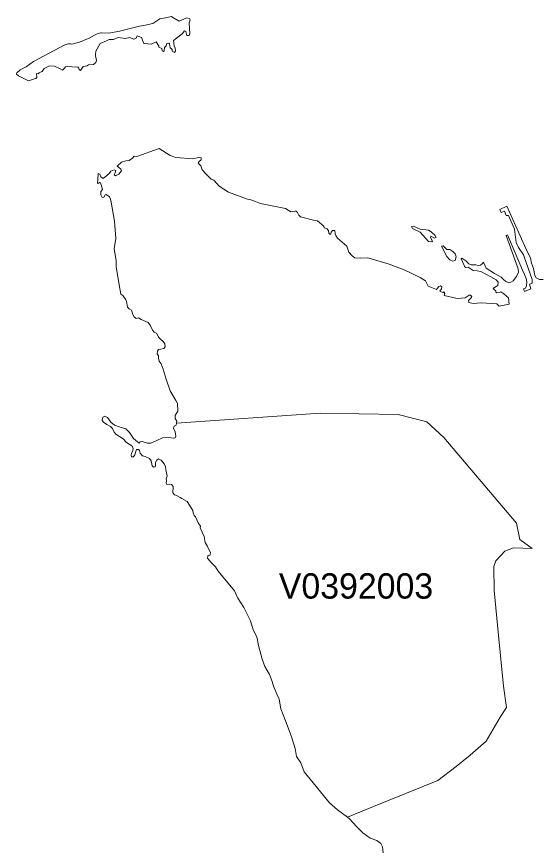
# Model space of a CAD drawing. Extents: x 369010 to 735936, y 6377141 to 6616555.
# Drawn here: x 409820 to 411897, y 6537827 to 6541117 of the extents above; entities that cross this region are included whole.
import ezdxf
from ezdxf.enums import TextEntityAlignment as Align

# ---------------------------------------------------------------- set-up
doc = ezdxf.new("R2010")
doc.units = 0
doc.header["$LTSCALE"] = 40
doc.layers.add('3', color=7, linetype='Continuous', lineweight=13)
doc.layers.add('4', color=7, linetype='Continuous')

msp = doc.modelspace()

# ---------------------------------------------------------------- linework, layer by layer
at = {"layer": '3'}
for points in [[(410420.8, 6541012.78), (410423.94, 6541009.31), (410426.26, 6540994.08), (410431.39, 6540989.12), (410433.87, 6540986.8), (410434.7, 6540981.17), (410442.97, 6540975.71), (410447.11, 6540981.5), (410447.11, 6540981.5), (410446.45, 6540992.26), (410446.45, 6540992.26), (410441.98, 6541001.03), (410439.5, 6541023.21), (410450.75, 6541031.65), (410473.43, 6541048.86), (410483.19, 6541060.28), (410488.32, 6541057.64), (410488.49, 6541057.64), (410491.63, 6541041.91), (410491.63, 6541041.91), (410501.56, 6541043.07), (410504.04, 6541048.53), (410500.9, 6541092.23), (410504.71, 6541104.8), (410502.72, 6541109.94), (410502.72, 6541109.94), (410491.14, 6541111.76), (410480.71, 6541107.29), (410461.84, 6541099.34), (410461.68, 6541099.18), (410436.35, 6541114.07), (410431.55, 6541116.89), (410412.69, 6541113.25), (410407.39, 6541112.09), (410385.71, 6541107.95), (410357.57, 6541089.25), (410327.29, 6541083.62), (410304.45, 6541079.48), (410231.79, 6541060.78), (410226.83, 6541059.46)], [(410226.83, 6541059.46), (410182.64, 6541052.01), (410155.49, 6541052.84), (410151.85, 6541053), (410138.12, 6541049.36), (410137.62, 6541049.2), (410127.19, 6541043.4), (410105.51, 6541031.32), (410067.94, 6541015.76), (410036.99, 6541008.81), (410032.19, 6541009.14), (410023.92, 6541009.81), (410009.68, 6541005.01), (409967.81, 6540982.99), (409885.72, 6540939.63), (409857.26, 6540919.27), (409833.75, 6540907.03), (409820.18, 6540895.28), (409819.52, 6540890.31), (409827.13, 6540882.7), (409827.13, 6540882.7), (409867.02, 6540863.67), (409877.78, 6540866.98), (409894.16, 6540871.94), (409895.49, 6540872.27), (409899.62, 6540876.08), (409897.47, 6540892.79), (409904.92, 6540891.14), (409904.92, 6540891.14), (409907.9, 6540894.28), (409919.65, 6540900.08), (409919.82, 6540900.08), (409928.42, 6540911.5), (409928.42, 6540911.5), (409946.79, 6540920.93), (409949.61, 6540922.42), (409969.47, 6540921.59), (409991.31, 6540910.5), (410000.58, 6540905.7), (410008.19, 6540913.81), (410012.5, 6540918.45), (410018.95, 6540920.27), (410060, 6540917.45), (410064.47, 6540916.79), (410066.29, 6540907.69), (410071.91, 6540903.88), (410072.08, 6540903.88), (410077.38, 6540912.32), (410082.51, 6540920.6), (410082.51, 6540920.6), (410098.56, 6540922.75), (410099.88, 6540923.74), (410103.03, 6540926.23), (410123.22, 6540927.55), (410123.22, 6540927.55), (410132.16, 6540935.49), (410135.14, 6540943.11), (410132.65, 6540956.35), (410131.83, 6540961.15), (410130.67, 6540967.11), (410132.98, 6540981.01), (410149.37, 6541010.8), (410174.36, 6541021.89), (410185.45, 6541026.85), (410189.92, 6541026.85), (410202.17, 6541026.85), (410204.98, 6541028.01), (410220.21, 6541034.47), (410250, 6541031.16), (410266.38, 6541033.97), (410281.94, 6541028.01), (410282.93, 6541027.68), (410291.37, 6541031.49), (410295.84, 6541040.59), (410295.84, 6541040.59), (410302.13, 6541038.77), (410313.22, 6541034.96), (410313.22, 6541034.96), (410319.67, 6541017.75), (410321.49, 6541012.95), (410322.16, 6541011.13), (410325.13, 6541010.8), (410351.28, 6541008.32), (410370.81, 6541016.92), (410380.74, 6541003.52), (410380.91, 6541003.35), (410381.57, 6540996.73), (410381.57, 6540996.73), (410392.99, 6540991.27), (410394.65, 6540982.33), (410394.65, 6540982.17), (410399.78, 6540979.19), (410399.94, 6540979.02), (410403.09, 6540982.17), (410403.75, 6540995.41), (410410.37, 6541002.03), (410412.36, 6541009.97), (410414.67, 6541010.8), (410420.8, 6541012.78), (410420.8, 6541012.78)], [(410599.21, 6540471.09), (410588.45, 6540474.57), (410579.18, 6540484.5), (410569.09, 6540493.93), (410552.37, 6540511.97), (410547.74, 6540528.02), (410542.44, 6540532.66), (410536.32, 6540539.44), (410540.29, 6540544.74), (410548.4, 6540550.7), (410548.4, 6540558.81), (410537.64, 6540560.13), (410516.29, 6540554.84), (410448.1, 6540560.79), (410426.75, 6540568.24), (410383.23, 6540595.55), (410294.35, 6540564.77), (410283.59, 6540565.43), (410277.64, 6540557.48), (410264.23, 6540548.71), (410250.82, 6540547.39), (410234.11, 6540541.43), (410217.39, 6540526.04), (410222.69, 6540522.07), (410231.46, 6540513.96), (410233.45, 6540508), (410223.35, 6540493.93), (410210.11, 6540487.97), (410204.65, 6540491.94), (410208.62, 6540499.89), (410211.43, 6540509.32), (410205.31, 6540511.97), (410191.9, 6540506.01), (410185.95, 6540498.56), (410176.51, 6540488.63), (410161.95, 6540477.88), (410151.85, 6540484.5), (410147.88, 6540494.59), (410141.76, 6540496.58), (410140.43, 6540471.92), (410139.11, 6540460.5), (410141.76, 6540457.85), (410147.22, 6540461.16), (410151.19, 6540459.84), (410155.16, 6540449.08), (410158.47, 6540434.35), (410152.51, 6540425.74), (410151.85, 6540412.34), (410157.15, 6540402.24), (410164.6, 6540403.56), (410169.23, 6540412.34), (410173.86, 6540413.66), (410185.95, 6540404.89), (410190.58, 6540396.28), (410193.23, 6540383.54), (410206.63, 6540309.23), (410212.1, 6540240.38), (410205.31, 6540199.66), (410212.76, 6540152.83), (410212.76, 6540129.32), (410224.67, 6540057.16), (410230.8, 6540021.08), (410238.74, 6540014.96), (410250.82, 6539998.25), (410254.13, 6539992.95), (410258.11, 6539968.79), (410264.89, 6539962.17), (410272.84, 6539957.53), (410278.3, 6539940.15), (410284.26, 6539931.38), (410291.54, 6539924.1), (410301.63, 6539927.41), (410311.73, 6539920.62), (410339.7, 6539908.71), (410347.15, 6539897.95), (410356.42, 6539877.92), (410363.2, 6539870.48), (410373.13, 6539864.52), (410380.58, 6539850.45), (410387.86, 6539843.17), (410398.62, 6539833.07), (410405.24, 6539823.64), (410405.9, 6539812.38), (410401.93, 6539806.26), (410389.85, 6539802.95), (410380.58, 6539801.63), (410375.78, 6539795.67), (410375.12, 6539784.91), (410379.92, 6539776.8), (410380.58, 6539767.53), (410382.56, 6539756.11), (410391.17, 6539745.52), (410399.28, 6539724.67), (410410.04, 6539683.95), (410426.75, 6539638.44), (410448.77, 6539599.71), (410455.39, 6539588.95), (410456.05, 6539557.51), (410446.12, 6539540.79), (410446.12, 6539528.71)], [(411762.21, 6540066.93), (411753.1, 6540069.91), (411744.33, 6540078.02), (411734.24, 6540087.62), (411707.59, 6540102.35), (411675.48, 6540123.04), (411664.72, 6540147.03), (411660.09, 6540140.41), (411652.64, 6540134.45), (411643.37, 6540133.13), (411634.6, 6540135.78), (411615.9, 6540135.78), (411606.63, 6540139.75), (411595.21, 6540151.83), (411579.16, 6540163.09), (411575.85, 6540160.44), (411589.25, 6540130.98), (411593.89, 6540125.68), (411603.82, 6540127.01), (411612.59, 6540121.71), (411623.35, 6540114.26), (411639.4, 6540112.94), (411654.79, 6540110.29), (411694.18, 6540088.94), (411714.21, 6540077.52), (411722.98, 6540067.59), (411721, 6540054.19), (411707.59, 6540047.4), (411703.45, 6540042.77), (411708.25, 6540037.47), (411713.55, 6540033.99), (411713.55, 6540028.7), (411716.86, 6540025.39), (411727.62, 6540027.37), (411733.57, 6540030.02), (411744.99, 6540022.08), (411763.03, 6540005.36), (411765.68, 6539981.2), (411726.95, 6539973.25), (411717.52, 6539982.52), (411655.46, 6539985.83), (411624.01, 6539983.85), (411607.29, 6539987.98), (411605.97, 6539995.27), (411614.58, 6540004.7), (411618.55, 6540011.32), (411613.25, 6540015.95), (411607.96, 6540016.62), (411591.9, 6540005.36), (411560.13, 6540002.88), (411509.32, 6540015.62), (411511.3, 6540023.07), (411507.33, 6540029.03), (411503.85, 6540027.04), (411491.94, 6540031.68), (411499.22, 6540041.11), (411500.54, 6540049.72), (411495.25, 6540053.85), (411488.63, 6540050.38), (411479.19, 6540039.12), (411445.76, 6540052.53), (411435, 6540072.56), (411414.98, 6540085.96), (411350.76, 6540116.75), (411292.01, 6540139.42), (411207.11, 6540164.08), (411180.29, 6540162.09), (411156.13, 6540164.08), (411146.2, 6540171.53), (411132.13, 6540186.26), (411124.85, 6540210.26), (411087.94, 6540241.7), (411081.32, 6540252.46), (411078.01, 6540258.42), (411077.35, 6540272.49), (411067.92, 6540271.82), (411063.28, 6540265.87), (411061.3, 6540257.09), (411057.32, 6540257.09), (411053.19, 6540261.89), (411051.86, 6540271.16), (411046.57, 6540278.61), (411034.49, 6540281.92), (411033.16, 6540289.2), (411008.5, 6540309.89), (410993.11, 6540312.7), (410940.98, 6540326.11), (410934.85, 6540332.07), (410930.22, 6540343.49), (410924.26, 6540348.12), (410919.46, 6540348.12), (410902.74, 6540345.47), (410882.72, 6540358.88), (410783.75, 6540378.9), (410763.72, 6540386.85), (410745.68, 6540392.97), (410732.27, 6540396.28), (410657.3, 6540423.09), (410620.56, 6540447.75), (410599.21, 6540471.09)], [(411901.06, 6540078.51), (411886.67, 6540078.02), (411872.6, 6540085.3), (411867.8, 6540094.57), (411862.01, 6540121.55), (411853.9, 6540142.73), (411849.92, 6540163.42), (411837.84, 6540189.07), (411804.58, 6540262.89), (411757.41, 6540368.48), (411729.93, 6540355.07), (411735.23, 6540343.49), (411747.31, 6540348.78), (411754.92, 6540331.9), (411763.2, 6540331.4), (411786.87, 6540276.79), (411789.68, 6540256.1), (411793.98, 6540225.15), (411803.75, 6540205.46), (411822.95, 6540175.5), (411826.09, 6540168.05), (411856.54, 6540077.85), (411856.54, 6540063.95), (411846.78, 6540059.48), (411852.07, 6540042.1), (411827.08, 6540031.01), (411823.44, 6540041.44), (411831.22, 6540044.42), (411835.03, 6540053.52), (411836.02, 6540069.41), (411833.54, 6540082.98), (411826.42, 6540097.88), (411818.64, 6540115.75), (411808.55, 6540139.92), (411759.72, 6540254.61), (411754.43, 6540252.79), (411802.26, 6540121.05), (411802.75, 6540106.98), (411795.47, 6540090.1), (411781.57, 6540073.22), (411772.3, 6540067.43), (411762.21, 6540066.93)], [(410744.36, 6538729.49), (410754.95, 6538694.57), (410769.02, 6538666.6), (410775.14, 6538631.68), (410790.37, 6538578.88), (410800.46, 6538549.42), (410819.16, 6538517.98), (410829.92, 6538490.01), (410834.56, 6538471.31), (410848.62, 6538437.05), (410857.23, 6538420.33), (410864.02, 6538381.6), (410882.06, 6538334.1), (410904.73, 6538275.85), (410920.78, 6538225.04), (410925.58, 6538193.59), (410942.3, 6538168.27), (410956.2, 6538133.51), (411056.66, 6538010.38), (411087.28, 6537983.57), (411126.84, 6537953.44), (411127, 6537953.61), (411229.78, 6537996.47), (411484.82, 6538099.42), (411557.31, 6538154.86), (411611.93, 6538198.72), (411675.15, 6538254), (411730.76, 6538349.66), (411755.75, 6538387.23), (411743.17, 6538471.47), (411723.48, 6538671.9), (411707.42, 6538849.98), (411705.6, 6538944.32), (411713.71, 6538966.66), (411749.46, 6539005.22), (411783.39, 6539018.63), (411856.87, 6539014.99), (411808.55, 6539050.73), (411795.14, 6539115.28), (411507.83, 6539453.57), (411440.8, 6539516.63), (411327.92, 6539545.26), (411019.26, 6539550.72), (410451.41, 6539511.33)], [(410451.41, 6539511.33), (411019.26, 6539550.72), (411327.92, 6539545.26), (411440.8, 6539516.63), (411507.83, 6539453.57), (411795.14, 6539115.28), (411808.55, 6539050.73), (411856.87, 6539014.99), (411783.39, 6539018.63), (411749.46, 6539005.22), (411713.71, 6538966.66), (411705.6, 6538944.32), (411707.42, 6538849.98), (411723.48, 6538671.9), (411743.17, 6538471.47), (411755.75, 6538387.23), (411730.76, 6538349.66), (411675.15, 6538254), (411611.93, 6538198.72), (411557.31, 6538154.86), (411484.82, 6538099.42), (411229.78, 6537996.47), (411127, 6537953.61), (411126.84, 6537953.44), (411135.44, 6537946.82), (411163.58, 6537915.38), (411187.58, 6537892.04), (411216.37, 6537871.19), (411242.52, 6537861.26), (411258.58, 6537850.5), (411265.86, 6537836.43), (411267.85, 6537813.1)], [(410451.41, 6539511.33), (410450.09, 6539503.39), (410441.98, 6539499.25), (410439.99, 6539491.31), (410445.46, 6539475.91), (410448.1, 6539459.86), (410445.46, 6539453.08), (410438.01, 6539451.09), (410423.28, 6539454.4), (410396.63, 6539452.41), (410373.13, 6539441.82), (410350.46, 6539431.73), (410337.05, 6539431.73), (410315.7, 6539437.68), (410307.59, 6539437.02), (410303.62, 6539431.73), (410297.66, 6539436.36), (410280.95, 6539449.76), (410266.22, 6539473.93), (410251.49, 6539488), (410228.15, 6539495.28), (410206.63, 6539502.56), (410191.9, 6539514.64), (410178.66, 6539532.68), (410168.57, 6539538.81), (410159.96, 6539534.01), (410157.81, 6539521.43), (410163.27, 6539514.64), (410176.51, 6539505.37), (410190.58, 6539497.93), (410198.03, 6539489.32), (410205.31, 6539475.25), (410212.1, 6539467.14), (410240.07, 6539449.1), (410254.13, 6539433.71), (410264.23, 6539428.41), (410274.16, 6539421.63), (410280.28, 6539412.36), (410278.96, 6539401.6), (410272.84, 6539392.34), (410271.51, 6539384.23), (410273.5, 6539378.27), (410280.95, 6539377.61), (410286.9, 6539385.55), (410289.55, 6539394.98), (410292.86, 6539406.24), (410301.63, 6539407.06), (410304.94, 6539402.27), (410308.25, 6539391.67), (410316.36, 6539382.24), (410327.12, 6539378.93), (410344.5, 6539371.48), (410351.12, 6539362.21), (410355.09, 6539342.19), (410359.89, 6539337.39), (410367.17, 6539338.05), (410368.5, 6539344.17), (410368.5, 6539354.77), (410373.13, 6539364.2), (410379.92, 6539369.5), (410390.51, 6539364.86), (410402.59, 6539350.13), (410407.22, 6539338.05), (410409.21, 6539327.46), (410414.01, 6539303.29), (410410.04, 6539290.55), (410412.02, 6539284.59), (410410.04, 6539273.17), (410413.35, 6539268.54), (410419.31, 6539269.2), (410431.39, 6539268.54), (410438.01, 6539260.43), (410437.35, 6539235.11), (410442.81, 6539227), (410448.77, 6539226.33), (410466.14, 6539217.07), (410472.76, 6539213.09), (410493.62, 6539201.67), (410516.29, 6539166.26), (410516.95, 6539156.82), (410520.93, 6539145.4), (410526.39, 6539140.77), (410536.98, 6539116.77), (410545.75, 6539104.03), (410545.09, 6539096.58), (410561.14, 6539062.49), (410565.12, 6539039.15), (410573.06, 6539025.74), (410585.14, 6538998.93), (410582.49, 6538988.34), (410576.54, 6538989.66), (410575.21, 6538985.53), (410574.38, 6538977.58), (410586.47, 6538962.19), (410605.17, 6538942.83), (410615.93, 6538925.45), (410680.14, 6538847.83), (410693.55, 6538819.03), (410716.88, 6538782.29), (410744.36, 6538729.49)], [(410446.12, 6539528.71), (410452.74, 6539518.61), (410451.41, 6539511.33)]]:
    msp.add_lwpolyline(points, dxfattribs=at)
for points in [[(411413.99, 6540277.12), (411388.33, 6540289.37), (411380.72, 6540287.88), (411384.2, 6540280.43), (411413.82, 6540265.04), (411447.91, 6540229.12), (411460.66, 6540227.14), (411463.31, 6540229.79), (411455.53, 6540244.85), (411456.85, 6540249.98), (411470.75, 6540241.37), (411477.7, 6540243.85), (411472.91, 6540252.96), (411458.01, 6540267.35), (411446.76, 6540273.48)], [(411543.08, 6540189.57), (411531.82, 6540197.51), (411520.07, 6540196.68), (411505.01, 6540211.75), (411498.23, 6540210.09), (411520.4, 6540169.05), (411531.16, 6540155.97), (411543.08, 6540150.34), (411552.68, 6540152.83), (411556.65, 6540168.55), (411552.68, 6540179.14)]]:
    msp.add_lwpolyline(points, close=True, dxfattribs=at)

# ---------------------------------------------------------------- texts
at = {"layer": '4'}
msp.add_text('V0392003', height=100, dxfattribs=at).set_placement((411160.82, 6538817.57), align=Align.CENTER)

doc.saveas('drawing.dxf')
